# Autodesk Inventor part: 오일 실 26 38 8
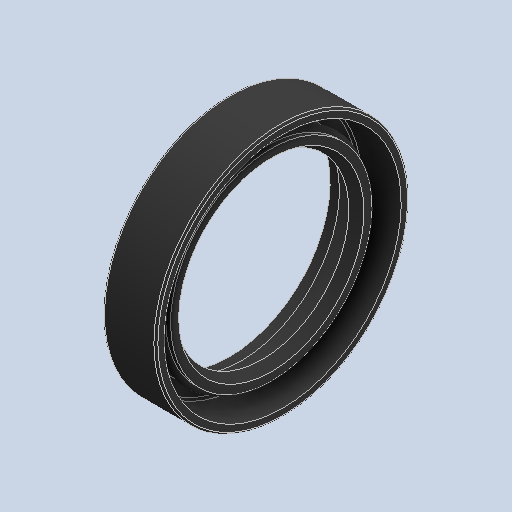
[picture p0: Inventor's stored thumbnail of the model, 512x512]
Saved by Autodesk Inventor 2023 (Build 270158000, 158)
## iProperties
Created: 2025-03
Part Number: 오일 실 26 38 8
Material: 고무
Description: 오일-실
Document SubType Name: Modeling
Designer: user
Density: 0.93 g/cm^3
Appearance: 기본값
Author: jhkim
Sending System: Autodesk Inventor 2025
Preprocessor: ST-DEVELOPER v20
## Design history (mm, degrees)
feature "Solid1"
node "솔리드1"
